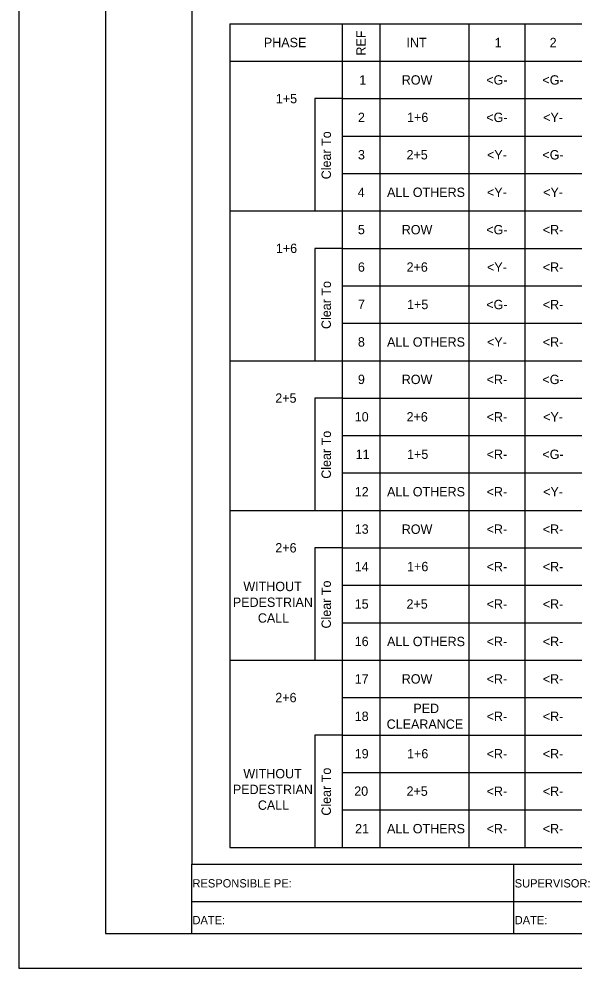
# Model space of a CAD drawing. Extents: x 515543 to 517243, y 660510 to 662861.
# Drawn here: x 515543 to 515944, y 660510 to 661197 of the extents above; entities that cross this region are included whole.
import ezdxf

# ---------------------------------------------------------------- set-up
doc = ezdxf.new("R2010")
doc.units = 0
for name, color, linetype in [('ANNO-TXT', 7, 'Continuous'), ('AXIS', 7, 'Continuous'), ('Default', 7, 'Continuous'), ('Level 62', 7, 'Continuous'), ('SHT-BDR', 7, 'Continuous'), ('SHT-BNDRY', 7, 'Continuous')]:
    doc.layers.add(name, color=color, linetype=linetype)

msp = doc.modelspace()

# ---------------------------------------------------------------- linework, layer by layer
at = {"layer": 'AXIS'}
msp.add_line((515667.5, 661135.25), (515667.5, 661135.3), dxfattribs=at)
at = {"layer": 'Default'}
for p, q in [((515695.04, 661193.38), (516385.67, 661193.38)), ((515695.04, 661193.38), (515695.04, 661057.96)), ((515776.29, 661193.38), (515776.29, 660597.54)), ((515803.37, 661193.38), (515803.37, 660597.54)), ((515867.73, 661193.38), (515867.73, 660597.54)), ((515908.35, 661193.38), (515908.35, 660597.54)), ((515695.04, 661166.29), (516385.67, 661166.29)), ((515776.29, 661139.21), (515756.47, 661139.21)), ((515756.47, 661139.21), (515756.47, 661057.96)), ((515776.29, 661139.21), (516273.98, 661139.21)), ((515776.29, 661112.13), (516273.98, 661112.13)), ((515776.29, 661085.04), (516273.98, 661085.04)), ((515695.04, 661057.96), (516385.67, 661057.96)), ((515695.04, 661057.96), (515695.04, 660949.63)), ((515776.29, 661057.96), (515938.79, 661057.96)), ((515776.29, 661030.88), (515756.47, 661030.88)), ((515756.47, 661030.88), (515756.47, 660949.63)), ((515776.29, 661030.88), (516273.98, 661030.88)), ((515776.29, 661003.79), (516273.98, 661003.79)), ((515776.29, 660976.71), (516273.98, 660976.71)), ((515695.04, 660949.63), (515695.04, 660841.29)), ((515695.04, 660949.63), (516385.67, 660949.63)), ((515776.29, 660922.54), (515756.47, 660922.54)), ((515776.29, 660922.54), (515756.47, 660922.54)), ((515756.47, 660922.54), (515756.47, 660841.29)), ((515776.29, 660922.54), (516263.79, 660922.54)), ((515776.29, 660922.54), (516273.98, 660922.54)), ((515776.29, 660895.46), (516273.98, 660895.46)), ((515776.29, 660895.46), (516273.98, 660895.46)), ((515776.29, 660868.38), (516263.79, 660868.38)), ((515776.29, 660868.38), (516273.98, 660868.38)), ((515695.04, 660841.29), (515695.04, 660732.96)), ((515695.04, 660841.29), (516385.67, 660841.29)), ((515776.29, 660814.21), (515756.47, 660814.21)), ((515776.29, 660814.21), (515756.47, 660814.21)), ((515756.47, 660814.21), (515756.47, 660732.96)), ((515776.29, 660814.21), (516263.79, 660814.21)), ((515776.29, 660814.21), (516273.98, 660814.21)), ((515776.29, 660787.13), (516273.98, 660787.13)), ((515776.29, 660787.13), (516273.98, 660787.13)), ((515776.29, 660760.04), (516263.79, 660760.04)), ((515776.29, 660760.04), (516273.98, 660760.04)), ((515695.04, 660732.96), (515695.04, 660597.54)), ((515695.04, 660732.96), (516385.67, 660732.96)), ((515776.29, 660705.88), (516263.79, 660705.88)), ((515776.29, 660705.88), (516273.98, 660705.88)), ((515776.29, 660678.79), (515756.47, 660678.79)), ((515776.29, 660678.79), (515756.47, 660678.79)), ((515756.47, 660678.79), (515756.47, 660597.54)), ((515776.29, 660678.79), (516273.98, 660678.79)), ((515776.29, 660678.79), (516273.98, 660678.79)), ((515776.29, 660651.71), (516263.79, 660651.71)), ((515776.29, 660651.71), (516273.98, 660651.71)), ((515776.29, 660624.63), (516273.98, 660624.63)), ((515776.29, 660624.63), (516263.79, 660624.63)), ((515776.29, 660624.63), (516263.79, 660624.63)), ((515695.04, 660597.54), (516385.67, 660597.54))]:
    msp.add_line(p, q, dxfattribs=at)
at = {"layer": 'Level 62'}
msp.add_lwpolyline([(515542.51, 660510.25), (517242.52, 660510.25), (517242.52, 661610.25), (515542.51, 661610.25)], close=True, dxfattribs=at)
at = {"layer": 'SHT-BDR'}
msp.add_lwpolyline([(515667.5, 660585.3), (517167.5, 660585.3), (517167.5, 661535.3), (515667.5, 661535.3)], close=True, dxfattribs=at)
at = {"layer": 'SHT-BNDRY'}
for p, q in [((515667.5, 660535.25), (515667.5, 660585.3)), ((515900.11, 660585.3), (515900.11, 660535.25)), ((515667.5, 660558.3), (516445.64, 660558.3))]:
    msp.add_line(p, q, dxfattribs=at)
msp.add_lwpolyline([(515605.01, 660535.25), (517217.52, 660535.25), (517217.52, 661585.25), (515605.01, 661585.25)], close=True, dxfattribs=at)

# ---------------------------------------------------------------- texts
at = {"layer": 'ANNO-TXT'}
for s, p in [('RESPONSIBLE PE:', (515667.97, 660568.52)), ('SUPERVISOR:', (515900.99, 660568.52)), ('DATE:', (515667.97, 660541.92)), ('DATE:', (515900.99, 660541.92))]:
    msp.add_text(s, height=6, rotation=360, dxfattribs=at).set_placement(p)
at = {"layer": 'Default'}
for s, p in [('REF', (515793.22, 661170.37)), ('Clear To', (515768.08, 661080.86)), ('Clear To', (515768.08, 660972.53)), ('Clear To', (515768.08, 660864.2)), ('Clear To', (515768.08, 660755.86)), ('Clear To', (515768.08, 660620.45))]:
    msp.add_text(s, height=6.771, rotation=90, dxfattribs=at).set_placement(p)
for s, height, p in [('PHASE', 6.771, (515719.62, 661176.45)), ('INT', 6.771, (515822.72, 661176.45)), ('1', 6.77, (515886.47, 661176.44)), ('2', 6.77, (515926.28, 661176.44)), ('1', 6.77, (515788.59, 661149.35)), ('ROW', 6.771, (515819.32, 661149.36)), ('<G-', 6.771, (515880.43, 661149.36)), ('<G-', 6.771, (515921.05, 661149.36)), ('1+5', 6.771, (515728.27, 661135.87)), ('2', 6.77, (515787.59, 661122.27)), ('1+6', 6.771, (515823.17, 661122.33)), ('<G-', 6.771, (515880.43, 661122.28)), ('<Y-', 6.771, (515921.58, 661122.28)), ('3', 6.77, (515787.62, 661095.24)), ('2+5', 6.771, (515822.76, 661095.24)), ('<Y-', 6.771, (515880.95, 661095.2)), ('<G-', 6.771, (515921.05, 661095.2)), ('4', 6.77, (515787.49, 661068.12)), ('ALL OTHERS', 6.771, (515808.67, 661068.11)), ('<Y-', 6.771, (515880.95, 661068.12)), ('<Y-', 6.771, (515921.58, 661068.12)), ('5', 6.77, (515787.59, 661041.13)), ('ROW', 6.771, (515819.32, 661041.03)), ('<G-', 6.771, (515880.43, 661041.03)), ('<R-', 6.771, (515921.32, 661041.03)), ('1+6', 6.771, (515728.29, 661027.54)), ('6', 6.77, (515787.6, 661013.99)), ('2+6', 6.771, (515822.79, 661013.99)), ('<Y-', 6.771, (515880.95, 661013.95)), ('<R-', 6.771, (515921.32, 661013.95)), ('7', 6.77, (515787.64, 660986.91)), ('1+5', 6.771, (515823.14, 660986.91)), ('<G-', 6.771, (515880.43, 660986.86)), ('<R-', 6.771, (515921.32, 660986.87)), ('8', 6.77, (515787.6, 660959.83)), ('ALL OTHERS', 6.771, (515808.67, 660959.78)), ('<Y-', 6.771, (515880.95, 660959.78)), ('<R-', 6.771, (515921.32, 660959.78)), ('9', 6.77, (515787.61, 660932.74)), ('ROW', 6.771, (515819.32, 660932.7)), ('ROW', 6.771, (515819.32, 660932.7)), ('<R-', 6.771, (515880.69, 660932.7)), ('<G-', 6.771, (515921.05, 660932.7)), ('<G-', 6.771, (515921.05, 660932.7)), ('2+5', 6.771, (515727.84, 660919.2)), ('10', 6.771, (515785.31, 660905.66)), ('2+6', 6.771, (515822.79, 660905.66)), ('<R-', 6.771, (515880.69, 660905.62)), ('<Y-', 6.771, (515921.58, 660905.62)), ('<Y-', 6.771, (515921.58, 660905.62)), ('11', 6.771, (515785.96, 660878.52)), ('1+5', 6.771, (515823.14, 660878.58)), ('<R-', 6.771, (515880.69, 660878.53)), ('<G-', 6.771, (515921.05, 660878.53)), ('<G-', 6.771, (515921.05, 660878.53)), ('12', 6.771, (515785.34, 660851.44)), ('ALL OTHERS', 6.771, (515808.67, 660851.45)), ('ALL OTHERS', 6.771, (515808.67, 660851.45)), ('<R-', 6.771, (515880.69, 660851.45)), ('<Y-', 6.771, (515921.58, 660851.45)), ('<Y-', 6.771, (515921.58, 660851.45)), ('13', 6.771, (515785.3, 660824.41)), ('ROW', 6.771, (515819.32, 660824.36)), ('ROW', 6.771, (515819.32, 660824.36)), ('<R-', 6.771, (515880.69, 660824.37)), ('<R-', 6.771, (515921.32, 660824.37)), ('2+6', 6.771, (515727.87, 660810.87)), ('14', 6.771, (515785.32, 660797.27)), ('1+6', 6.771, (515823.17, 660797.33)), ('1+6', 6.771, (515823.17, 660797.33)), ('<R-', 6.771, (515880.69, 660797.28)), ('<R-', 6.771, (515921.32, 660797.28)), ('WITHOUT', 6.771, (515704.76, 660782.92)), ('PEDESTRIAN', 6.771, (515697.19, 660771.52)), ('15', 6.771, (515785.28, 660770.24)), ('2+5', 6.771, (515822.76, 660770.24)), ('2+5', 6.771, (515822.76, 660770.24)), ('<R-', 6.771, (515880.69, 660770.2)), ('<R-', 6.771, (515921.32, 660770.2)), ('CALL', 6.771, (515715.25, 660760.11)), ('16', 6.771, (515785.3, 660743.16)), ('ALL OTHERS', 6.771, (515808.67, 660743.11)), ('ALL OTHERS', 6.771, (515808.67, 660743.11)), ('<R-', 6.771, (515880.69, 660743.12)), ('<R-', 6.771, (515921.32, 660743.12)), ('17', 6.771, (515785.3, 660716.02)), ('ROW', 6.771, (515819.32, 660716.03)), ('ROW', 6.771, (515819.32, 660716.03)), ('<R-', 6.771, (515880.69, 660716.03)), ('<R-', 6.771, (515921.32, 660716.03)), ('2+6', 6.771, (515727.87, 660702.54)), ('PED', 6.771, (515827.7, 660694.71)), ('18', 6.771, (515785.3, 660688.99)), ('<R-', 6.771, (515880.69, 660688.95)), ('<R-', 6.771, (515921.32, 660688.95)), ('CLEARANCE', 6.771, (515808.38, 660683.31)), ('19', 6.771, (515785.3, 660661.91)), ('1+6', 6.771, (515823.17, 660661.91)), ('<R-', 6.771, (515880.69, 660661.87)), ('<R-', 6.771, (515921.32, 660661.87)), ('WITHOUT', 6.771, (515704.76, 660647.5)), ('PEDESTRIAN', 6.771, (515697.19, 660636.1)), ('20', 6.771, (515784.94, 660634.83)), ('2+5', 6.771, (515822.76, 660634.83)), ('<R-', 6.771, (515880.69, 660634.78)), ('<R-', 6.771, (515921.32, 660634.78)), ('CALL', 6.771, (515715.25, 660624.7)), ('21', 6.771, (515785.58, 660607.69)), ('ALL OTHERS', 6.771, (515808.67, 660607.7)), ('ALL OTHERS', 6.771, (515808.67, 660607.7)), ('<R-', 6.771, (515880.69, 660607.7)), ('<R-', 6.771, (515921.32, 660607.7))]:
    msp.add_text(s, height=height, dxfattribs=at).set_placement(p)

doc.saveas('drawing.dxf')
